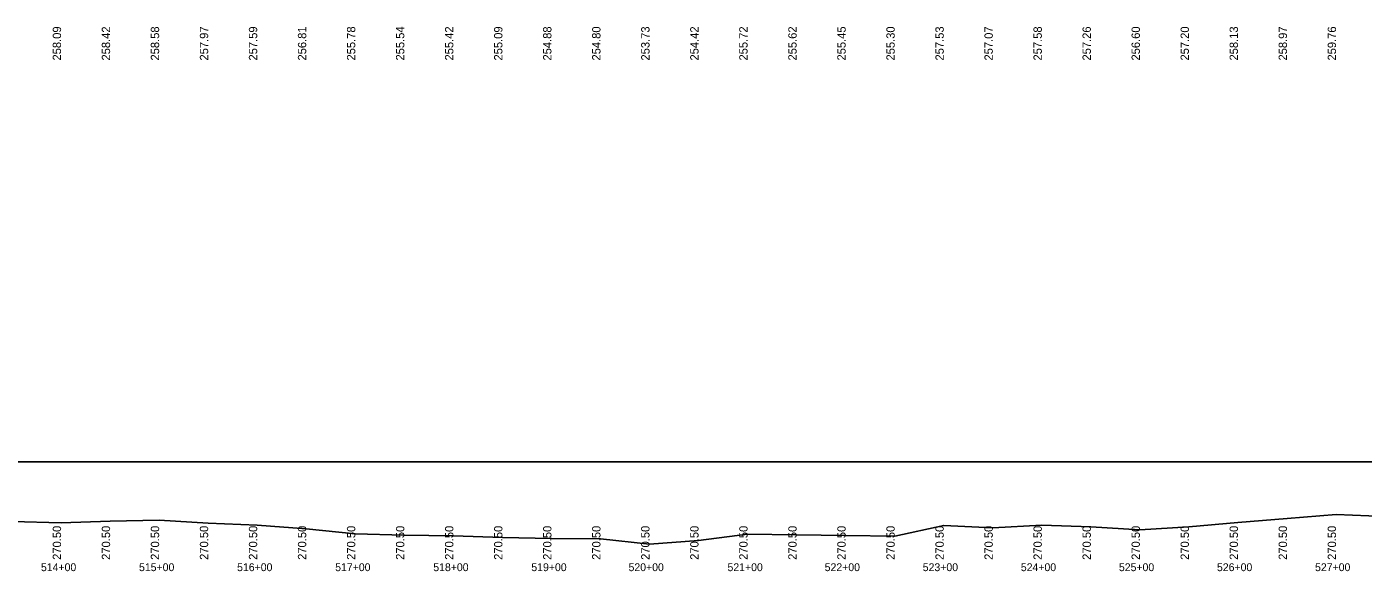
# Model space of a CAD drawing. Extents: x 49241 to 62599, y 49216 to 56011.
# Drawn here: x 59849 to 61212, y 53749 to 54304 of the extents above; entities that cross this region are included whole.
import ezdxf

# ---------------------------------------------------------------- set-up
doc = ezdxf.new("R2010")
doc.units = 0
for name, color, linetype in [('Level 40', 7, 'Continuous'), ('Level 42', 7, 'Continuous'), ('Level 43', 7, 'Continuous'), ('Level 45', 7, 'Continuous')]:
    doc.layers.add(name, color=color, linetype=linetype)

msp = doc.modelspace()

# ---------------------------------------------------------------- linework, layer by layer
at = {"layer": 'Level 40'}
msp.add_lwpolyline([(59834.2, 53799.3), (59884.2, 53798.2), (59934.2, 53799.9), (59984.2, 53800.7), (60034.2, 53797.6), (60084.2, 53795.8), (60134.2, 53791.8), (60184.2, 53786.7), (60234.2, 53785.5), (60284.2, 53784.9), (60334.2, 53783.2), (60384.2, 53782.2), (60434.2, 53781.8), (60484.2, 53776.4), (60534.2, 53779.9), (60584.2, 53786.4), (60634.2, 53785.9), (60684.2, 53785), (60734.2, 53784.3), (60784.2, 53795.4), (60834.2, 53793.1), (60884.2, 53795.7), (60934.2, 53794.1), (60984.2, 53790.8), (61034.2, 53793.8), (61084.2, 53798.5), (61134.2, 53802.6), (61184.2, 53806.6), (61234.2, 53804.6)], dxfattribs=at)
at = {"layer": 'Level 45'}
msp.add_line((58984.2, 53860.3), (61684.2, 53860.3), dxfattribs=at)

# ---------------------------------------------------------------- texts
at = {"layer": 'Level 42'}
for s, p in [('514+00', (59863.7, 53748.8)), ('515+00', (59963.7, 53748.8)), ('516+00', (60063.7, 53748.8)), ('517+00', (60163.7, 53748.8)), ('518+00', (60263.7, 53748.8)), ('519+00', (60363.7, 53748.8)), ('520+00', (60462.8, 53748.8)), ('521+00', (60563.7, 53748.8)), ('522+00', (60662.8, 53748.8)), ('523+00', (60762.8, 53748.8)), ('524+00', (60862.8, 53748.8)), ('525+00', (60962.8, 53748.8)), ('526+00', (61062.8, 53748.8)), ('527+00', (61162.8, 53748.8))]:
    msp.add_text(s, height=8, dxfattribs=at).set_placement(p)
at = {"layer": 'Level 43'}
for s, p in [('258.09', (59884.2, 54269.3)), ('258.42', (59934.2, 54269.3)), ('258.58', (59984.2, 54269.3)), ('257.97', (60034.2, 54269.3)), ('257.59', (60084.2, 54269.3)), ('256.81', (60134.2, 54269.3)), ('255.78', (60184.2, 54269.3)), ('255.54', (60234.2, 54269.3)), ('255.42', (60284.2, 54269.3)), ('255.09', (60334.2, 54269.3)), ('254.88', (60384.2, 54269.3)), ('254.80', (60434.2, 54269.3)), ('253.73', (60484.2, 54269.3)), ('254.42', (60534.2, 54269.3)), ('255.72', (60584.2, 54269.3)), ('255.62', (60634.2, 54269.3)), ('255.45', (60684.2, 54269.3)), ('255.30', (60734.2, 54269.3)), ('257.53', (60784.2, 54269.3)), ('257.07', (60834.2, 54269.3)), ('257.58', (60884.2, 54269.3)), ('257.26', (60934.2, 54269.3)), ('256.60', (60984.2, 54269.3)), ('257.20', (61034.2, 54269.3)), ('258.13', (61084.2, 54269.3)), ('258.97', (61134.2, 54269.3)), ('259.76', (61184.2, 54269.3)), ('270.50', (59884.2, 53760.3)), ('270.50', (59934.2, 53760.3)), ('270.50', (59984.2, 53760.3)), ('270.50', (60034.2, 53760.3)), ('270.50', (60084.2, 53760.3)), ('270.50', (60134.2, 53760.3)), ('270.50', (60184.2, 53760.3)), ('270.50', (60234.2, 53760.3)), ('270.50', (60284.2, 53760.3)), ('270.50', (60334.2, 53760.3)), ('270.50', (60384.2, 53760.3)), ('270.50', (60434.2, 53760.3)), ('270.50', (60484.2, 53760.3)), ('270.50', (60534.2, 53760.3)), ('270.50', (60584.2, 53760.3)), ('270.50', (60634.2, 53760.3)), ('270.50', (60684.2, 53760.3)), ('270.50', (60734.2, 53760.3)), ('270.50', (60784.2, 53760.3)), ('270.50', (60834.2, 53760.3)), ('270.50', (60884.2, 53760.3)), ('270.50', (60934.2, 53760.3)), ('270.50', (60984.2, 53760.3)), ('270.50', (61034.2, 53760.3)), ('270.50', (61084.2, 53760.3)), ('270.50', (61134.2, 53760.3)), ('270.50', (61184.2, 53760.3))]:
    msp.add_text(s, height=8.5, rotation=90, dxfattribs=at).set_placement(p)

doc.saveas('drawing.dxf')
